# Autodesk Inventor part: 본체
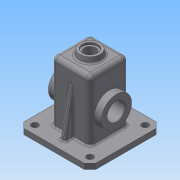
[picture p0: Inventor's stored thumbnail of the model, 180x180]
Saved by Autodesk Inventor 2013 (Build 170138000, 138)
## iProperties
Created: 2016-02
Part Number: 본체
Material: 일반
Document SubType Name: Modeling
Designer: Administrator
Density: 1 g/cm^3
Author: Administrator
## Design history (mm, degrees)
sketch "스케치1"
  geometry: L1 (-35, 0)-(35, 0); L2 (-35, 35)-(35, 35); L3 (35, 35)-(35, -35); L4 (35, -35)-(-35, -35); L5 (-35, -35)-(-35, 35); 2 further points
  constraints: 10 end point, 2 horizontal, 2 midpoint, 2 parallel, 1 coincident, 1 perpendicular
  dimensions: "d0" = 70 distance of L1.start L1.end; "d1" = 70 distance of L3.end L4.end; "d2" = 70 distance of L2.end L3.end
extrude "돌출1" new body sketch "스케치1" distance "d3" = 120; taper "d4" = 0 deg
sketch "스케치2"
  geometry: L1 (35, 35)-(-35, 35) reference; L2 (-35, 35)-(-35, -35) reference; L3 (-35, -35)-(35, -35) reference; L4 (35, -35)-(35, 35) reference; L5 (-65, 0)-(65, 0); L6 (-65, -65)-(65, -65); L7 (65, -65)-(65, 65); L8 (65, 65)-(-65, 65); L9 (-65, 65)-(-65, -65); 2 further points
  constraints: 10 end point, 2 midpoint, 2 parallel, 2 perpendicular, 1 coincident, 1 horizontal
  dimensions: "d5" = 130 distance of L5.start L5.end; "d6" = 130 distance of L8.end L7.end; "d7" = 130 distance of L7.end L6.end
extrude "돌출2" join sketch "스케치2" distance "d8" = 10; taper "d9" = 0 deg
chamfer "모따기1" distance "d10" = 10; stored, may be unused: second distance "d11" = 2, angle "d12" = 45 deg
sketch "스케치3"
  geometry: L1 (-65, 55)-(-65, -55) reference; L2 (0, 50)-(0, -50); L3 (-50, 50)-(50, 50); L4 (-50, -50)-(50, -50); C1 r 6 at (-50, 50); C2 r 6 at (50, 50); C3 r 6 at (-50, -50); C4 r 6 at (50, -50); 2 further points
  constraints: 6 end point, 5 coincident, 4 centre point, 3 midpoint, 2 parallel, 1 perpendicular
  dimensions: "d13" = 100 distance of L2.start L2.end; "d14" = 100 distance of L3.start L3.end; "d15" = 100 distance of L4.start L4.end; "d16" = 12 diameter of C1; "d17" = 12 diameter of C2; "d18" = 12 diameter of C3; "d19" = 12 diameter of C4
extrude "돌출3" cut sketch "스케치3" distance "d20" = 10; taper "d21" = 0 deg
fillet "모깎기1" dims "d22" = 8
sketch "스케치4"
  geometry: L1 (-27, 120)-(27, 120) reference; L2 (-20, 120)-(20, 120); L3 (0, 120)-(0, 130); L4 (-20, 120)-(-18.237, 130); L5 (-20, 120)-(-9.846, 120); L6 (-18.237, 130)-(0, 130); 1 further point
  constraints: 10 end point, 2 midpoint, 2 perpendicular, 1 collinear, 1 equal length, 1 horizontal
  dimensions: "d23" = 40 distance of L2.start L2.end; "d24" = 10 distance of L3.start L3.end; "d25" = 80 deg angle of L5 L4
revolve "회전1" sketch "스케치4" stored, may be unused: angle "d26" = 90 deg
sketch "스케치5"
  geometry: C1 r 18.237 at (0, 0) reference; C2 r 14 at (0, 0)
  constraints: 1 centre point, 1 coincident
  dimensions: "d27" = 28 diameter of C2
extrude "돌출4" cut sketch "스케치5" distance "d28" = 4; taper "d29" = 0 deg
sketch "스케치6"
  geometry: C1 r 14 at (0, 0) reference; C2 r 10.5 at (0, 0)
  constraints: 1 centre point, 1 coincident
  dimensions: "d30" = 21 diameter of C2
extrude "돌출5" cut sketch "스케치6" stored distance "d31" = 4; taper "d32" = 0 deg
sketch "스케치7"
  geometry: L1 (-65, 55)-(-65, -55) reference; L2 (-30, 0)-(30, 0); L3 (-30, -30)-(30, -30); L4 (30, -30)-(30, 30); L5 (30, 30)-(-30, 30); L6 (-30, 30)-(-30, -30); C1 r 10.5 at (0, 0) reference; 1 further point
  constraints: 10 end point, 2 midpoint, 2 parallel, 2 perpendicular, 1 coincident, 1 horizontal
  dimensions: "d33" = 60 distance of L2.start L2.end; "d34" = 60 distance of L5.end L4.end; "d35" = 60 distance of L4.end L3.end
extrude "돌출6" cut sketch "스케치7" distance "d36" = 115; taper "d37" = 0 deg
fillet "모깎기2" dims "d38" = 3
sketch "스케치8"
  geometry: L1 (-30, 112)-(-30, 0) reference; L2 (30, 0)-(30, 112) reference; L3 (-35, 10)-(-35, 112) reference; L4 (35, 112)-(35, 10) reference; L5 (27, 0)-(-27, 0) reference; L6 (0, 0)-(0, 55); L7 (-30, 82.5)-(-30, 27.5); L8 (-30, 0)-(-27, 0) reference; L9 (-30, 55)-(-23, 55); L10 (-30, 82.5)-(-23, 75.5); L11 (-23, 75.5)-(-23, 55); L12 (30, 55)-(23, 55); L13 (23, 75.5)-(23, 55); L14 (30, 82.5)-(23, 75.5); L15 (30, 82.5)-(30, 27.5)
  constraints: 18 end point, 5 symmetric about line, 2 perpendicular, 1 midpoint, 1 parallel
  dimensions: "d39" = 55 distance of L6.start L6.end; "d42" = 55 distance of L7.start L7.end; "d44" = 30 horizontal distance of L6.start L7.end; "d45" = 7 distance of L9.start L9.end; "d47" = 45 deg angle of L1 L10; "d48" = 55 distance from line of L6.start L9; "d49" = 23 distance from line of L6.end L11
revolve "회전2" sketch "스케치8" stored, may be unused: angle "d50" = 90 deg
sketch "스케치9"
  geometry: L1 (10, 82)-(10, -28) reference; L2 (10, 27)-(-45, 27); C1 r 20.5 at (-45, 27) reference; C2 r 27.5 at (-45, 27)
  constraints: 2 end point, 1 centre point, 1 coincident, 1 perpendicular
  dimensions: "d51" = 55 distance of L2.start L2.end; "d52" = 55 diameter of C2
extrude "돌출7" join sketch "스케치9" distance "d53" = 13; taper "d54" = 0 deg
sketch "스케치10"
  geometry: C1 r 27.5 at (0, 0) reference; C2 r 16 at (0, 0); 1 further point
  constraints: 1 centre point, 1 coincident
  dimensions: "d55" = 32 diameter of C2
extrude "돌출8" cut sketch "스케치10" stored distance "d56" = 13; taper "d57" = 0 deg
fillet "모깎기3" dims "d58" = 0.5
sketch "스케치11"
  geometry: C1 r 16 at (-57, 27) reference; C2 r 27.5 at (-57, 27); 1 further point
  constraints: 1 centre point, 1 coincident
  dimensions: "d59" = 55 diameter of C2
extrude "돌출9" join sketch "스케치11" distance "d60" = 13; taper "d61" = 0 deg
fillet "모깎기4" dims "d62" = 0.5
fillet "모깎기5" dims "d63" = 3
sketch "스케치12"
  geometry: L1 (35, 112)-(35, 10) reference; L2 (55, 10)-(-55, 10) reference; L3 (44, 10)-(56, 10) reference; L4 (55, 10)-(65, 10) reference; L5 (65, 10)-(50, 10); L6 (50, 10)-(35, 95.069); L7 (35, 95.069)-(35, 10); L8 (50, 10)-(35, 10); L9 (-10.5, 115)-(10.5, 115) reference; L10 (0, 0)-(0, 115); L11 (-50, 10)-(-35, 95.069); L12 (-35, 95.069)-(-35, 10); L13 (-44, 10)-(-56, 10); L14 (-55, 10)-(-65, 10); L15 (-65, 10)-(-50, 10); L16 (-50, 10)-(-35, 10)
  constraints: 22 end point, 6 symmetric about line, 3 midpoint, 2 collinear, 1 point on line
  dimensions: "d64" = 15 distance of L4.end L5.end; "d65" = 100 deg angle of L5 L6
extrude "돌출10" join sketch "스케치12" stored distance "d66" = 9; taper "d67" = 0 deg
fillet "모깎기6" dims "d68" = 3
sketch "스케치13"
  geometry: L1 (18, 8.763)-(18, 45.237) reference; L2 (18, 27)-(-12, 27); 2 further points
  constraints: 2 end point, 1 coincident, 1 midpoint, 1 perpendicular, 1 other
  dimensions: "d69" = 30 distance of L2.start L2.end
feature "엠보싱1" sketch "스케치13" dims "d70" = 0.5, "d71" = 0
fillet "모깎기7" dims "d72" = 0.5
sketch "스케치14"
  geometry: L1 (0, 22.5)-(0, -22.5); L2 (22.5, 0)-(-22.5, 0); C1 r 27.5 at (0, 0) reference; A1 r 22.5 centre (0, 0) between (0, 22.5) and (0, -22.5); 6 further points
  constraints: 5 coincident, 4 end point, 4 point on circle, 2 midpoint, 1 centre point, 1 perpendicular, 1 vertical
  dimensions: "d73" = 45 diameter of A1
hole "구멍1" sketch "스케치14" at (0, 22.5), (-22.5, 0), (0, -22.5), (22.5, 0) diameter "d74" = 3.242; stored, may be unused: countersink angle "d78" = 90 deg, drill point angle "d80" = 118 deg; dims "d75" = 8, "d76" = 4, "d77" = 2, "d79" = 10
sketch "스케치15"
  geometry: L1 (0, 22.5)-(0, -22.5); L2 (-22.5, 0)-(22.5, 0); C1 r 27.5 at (0, 0) reference; A1 r 22.5 centre (0, 0) between (0, 22.5) and (0, -22.5); 6 further points
  constraints: 5 coincident, 4 end point, 4 point on circle, 2 midpoint, 1 centre point, 1 perpendicular, 1 vertical
  dimensions: "d81" = 45 diameter of A1
hole "구멍2" sketch "스케치15" at (0, 22.5), (-22.5, 0), (0, -22.5), (22.5, 0) diameter "d82" = 3.242; stored, may be unused: countersink angle "d86" = 90 deg, drill point angle "d88" = 118 deg; dims "d83" = 8, "d84" = 4, "d85" = 2, "d87" = 10
chamfer "모따기2" distance "d89" = 1; stored, may be unused: second distance "d90" = 2, angle "d91" = 45 deg
node "솔리드1"
